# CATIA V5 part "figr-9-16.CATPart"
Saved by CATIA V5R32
Part number: Part1
Bounding box of the stored display mesh (mm): x -77.304 to 77.304, y -77.304 to 125.507, z 0 to 125
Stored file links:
  D:\PROJECTS\Project 2022\CATIA V5 6R 2022\Resources\Part Files\c09_catia_v5_6r2022_prt\c09_catia_v5_6r2022_prt\figr-9-16.CATPart
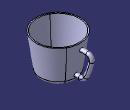
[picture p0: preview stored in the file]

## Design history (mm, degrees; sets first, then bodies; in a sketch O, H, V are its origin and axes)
Set1
  Plane1: type Normal, Curve Sketch3, RefPoint vertex of Sketch3
Body1 (main body)
  Sketch1 on yz-plane, origin (0, 0, 0), H (0, 1, 0), V (0, 0, 1)
    line L1 (0, 0) -> (60, 0)
    point P1 (60, 0)
    point P2 (60, 0)
    line L2 (60, 0) -> (77.5, 125)
    point P3 (77.5, 125)
    line L3 (77.5, 125) -> (0, 125)
    point P4 (0, 125)
    line L4 (0, 125) -> (0, 0)
    axis line L5 (0, 150.2858) -> (0, -31.0593)
    point P5 (0, 150.2858)
    radius about axis P1 L5 = 60
    radius about axis P3 L5 = 77.5
    distance L3 L1 = 125
    horizontal: L1 H, L3 H
    coincidence: P4 V, P2 P1, P5 V
    vertical: L4 V, L5 V
  Shaft1: profile Sketch1, axis Sketch1.L5, angle 360
  Fillet1: radius 15, on edge [face of Shaft1 | face of Shaft1]
  Shell1: ExtOffset 0, Face face of Shaft1, IntOffset 4
  Sketch2 on Plane1, origin (0, 62.9841, 0), H (-1, 0, 0), V (0, 0, 1)
    circle A1 centre (0, 22.002) radius 7.5
    reference projected point E1 (0, 22.002) from vertex of Sketch3
    radius A1 = 7.5
    concentricity: A1 E1
  Sketch3 on yz-plane, origin (0, 0, 0), H (0, 1, 0), V (0, 0, 1)
    line L1 (62.9841, 22.002) -> (78.2172, 22.002)
    arc A1 centre (78.2172, 44.1133) radius 22.1113 from (78.2172, 22.002) to (97.9307, 34.0988) ccw
    arc A2 centre (-112.3295, 140.9107) radius 235.8349 from (97.9307, 34.0988) to (117.8681, 89.6549) ccw
    arc A3 centre (104.0328, 92.7355) radius 14.1742 from (117.8681, 89.6549) to (104.4272, 106.9041) ccw
    arc A4 centre (93.6744, -279.4123) radius 386.4661 from (104.4272, 106.9041) to (82.9216, 106.9041) ccw
    horizontal: L1 H
    tangency: A1 L1, A2 A1, A3 A2, A4 A3
  Rib1: profile Sketch2, centre curve Sketch3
